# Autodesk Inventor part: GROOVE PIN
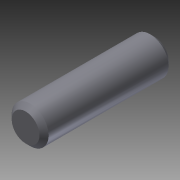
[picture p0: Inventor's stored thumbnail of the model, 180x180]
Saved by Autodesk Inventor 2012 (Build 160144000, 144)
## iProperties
Shininess: 64.0
Length Units: 11272
Angle Units: 11279
Time Units: 11290
Mass Units: 11286
Length Display Precision: 3
Angle Display Precision: 2
Compacted: True
Part Number: GROOVE PIN
Document SubType Name: Modeling
Created: 2003-11
Designer: Autodesk, Inc.
Manufacturer: Standard
Standards Organization: Custom
Mass: 5.44307 g
Surface Area: 4.86691 cm^2
Volume: 0.692502 cm^3
Density: 7.86 g/cm^3
Material: Steel, Mild
Density: 0.0
Volumn: 0.0
Area: 0.0
PropertySet Name: Model Information
Control State: 0
Master: False
Checked Out: False
Author: Autodesk, Inc.
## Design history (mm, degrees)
sketch "Sketch1"
  geometry: C1 r 3.175 at (0, 0); 1 further point
  constraints: 1 centre point, 1 coincident
  dimensions: "d0" = 6.35 diameter of C1
extrude "Extrusion1" new body sketch "Sketch1" distance "d1" = 22.225; taper "d2" = 0 deg
chamfer "Chamfer1" distance "d3" = 0.7874; stored, may be unused: second distance "d4" = 3.175, angle "d5" = 45 deg
body "Solid1"
